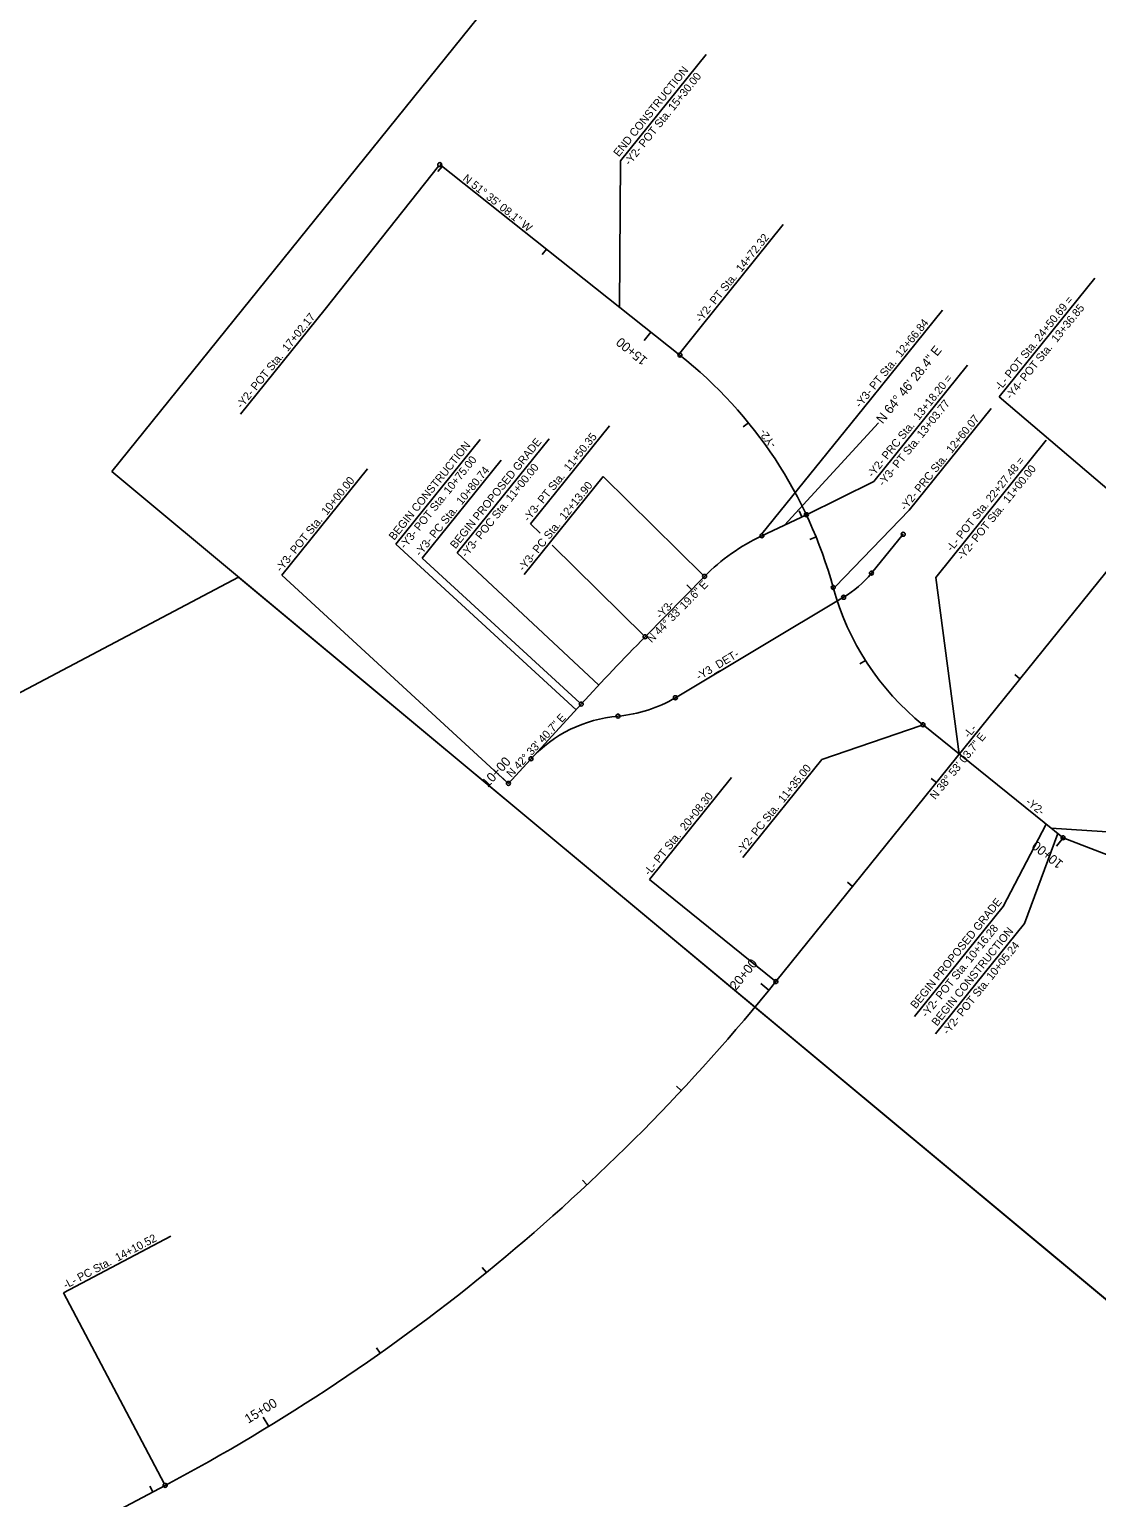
# Model space of a CAD drawing. Extents: x 1487008 to 1489561, y 497293 to 500195.
# Drawn here: x 1488013 to 1488814, y 498527 to 499628 of the extents above; entities that cross this region are included whole.
import ezdxf

# ---------------------------------------------------------------- set-up
doc = ezdxf.new("R2010")
doc.units = 0
for name, color, linetype in [('Prop Horizontal Alignment', 7, 'Continuous'), ('Prop Horizontal Alignment Direction Label', 7, 'Continuous'), ('Prop Horizontal Alignment Station Label', 7, 'Continuous'), ('Prop Horizontal Alignment Tick Label', 7, 'Continuous'), ('Prop Horizontal Alignment Tick Large', 7, 'Continuous'), ('Prop Horizontal Alignment Tick Small', 7, 'Continuous'), ('Scratch_Level_5', 7, 'Continuous')]:
    doc.layers.add(name, color=color, linetype=linetype)

msp = doc.modelspace()

# ---------------------------------------------------------------- linework, layer by layer
at = {"layer": 'Prop Horizontal Alignment'}
for p, q in [((1488501.1, 499383.6), (1488321, 499526.4)), ((1488573.1, 498913.9), (1489007.3, 499452.3)), ((1488562.6, 499248.1), (1488596, 499263.9)), ((1488644.8, 499220.1), (1488668.6, 499249.2)), ((1488475, 499172.4), (1488519.6, 499217.7)), ((1488497.7, 499126.7), (1488623.9, 499202)), ((1488372.5, 499062.5), (1488427.1, 499121.9)), ((1488788.6, 499021.7), (1488683.5, 499106.4)), ((1487752.2, 498344.1), (1488115, 498536.2))]:
    msp.add_line(p, q, dxfattribs=at)
for centre, radius, start, end in [((1488292.9, 499121.1), 335, 15.2846, 51.5856), ((1488626.5, 499112.4), 150, 115.2255, 135.4445), ((1488582.8, 499270.7), 80, 300.8418, 320.7375), ((1488809, 499262.1), 200, 195.2846, 231.1156), ((1489900.2, 497769.2), 2000, 135.4445, 137.4387), ((1488446.5, 499212.6), 100, 274.7509, 300.8418), ((1488463, 499013.2), 100, 94.7509, 137.4387), ((1487425, 499839.8), 1475, 297.895, 321.1156)]:
    msp.add_arc(centre, radius, start, end, dxfattribs=at)
at = {"layer": 'Prop Horizontal Alignment Direction Label'}
msp.add_line((1488779.7, 499028.8), (1488833.2, 499025.4), dxfattribs=at)
at = {"layer": 'Prop Horizontal Alignment Station Label'}
for p, q in [((1488456.6, 499529.3), (1488520.8, 499609)), ((1488320.1, 499525.2), (1488235.1, 499418.1)), ((1488455.9, 499419.4), (1488456.6, 499529.3)), ((1488517, 499405.1), (1488578.6, 499481.5)), ((1488740.7, 499352.4), (1488812.3, 499441.2)), ((1488171.6, 499339.3), (1488235.1, 499418.1)), ((1488638.8, 499343.8), (1488698, 499417.2)), ((1488501.1, 499385.1), (1488517, 499405.1)), ((1488646.7, 499288.9), (1488716.9, 499376)), ((1488740.7, 499352.4), (1488849.7, 499259.2)), ((1488562.6, 499249.6), (1488638.8, 499343.8)), ((1488673.1, 499267.3), (1488734.7, 499343.6)), ((1488389, 499257.1), (1488448.2, 499330.5)), ((1488650, 499332.7), (1488579.5, 499256.1)), ((1488288, 499241.8), (1488351.3, 499320.3)), ((1488334, 499235.4), (1488403, 499320.9)), ((1488693, 499216.9), (1488775.9, 499319.7)), ((1488307.9, 499231.4), (1488367.1, 499304.8)), ((1488202.5, 499218.5), (1488266.8, 499298.2)), ((1488384.4, 499219.1), (1488443.6, 499292.5)), ((1488443.6, 499292.5), (1488518.6, 499218.7)), ((1488596, 499263.9), (1488646.7, 499288.9)), ((1488617.5, 499209.8), (1488673.1, 499267.3)), ((1488396.2, 499250), (1488389, 499257.1)), ((1488423.2, 499117.7), (1488288, 499241.8)), ((1488474, 499173.4), (1488405.3, 499241)), ((1488426, 499122.9), (1488307.9, 499231.4)), ((1488440.2, 499136.1), (1488334, 499235.4)), ((1488371.4, 499063.5), (1488202.5, 499218.5)), ((1488693, 499216.9), (1488710.7, 499084.5)), ((1488682, 499105.9), (1488607.6, 499080.4)), ((1488548.4, 499007), (1488607.6, 499080.4)), ((1488478.3, 498990.4), (1488539.9, 499066.8)), ((1488775.9, 499031.9), (1488743.6, 498970.2)), ((1488759.5, 498957.4), (1488784.5, 499025)), ((1488788.6, 499021.7), (1488836.7, 499003.1)), ((1488572, 498914.8), (1488478.3, 498990.4)), ((1488677, 498887.7), (1488743.6, 498970.2)), ((1488692.9, 498874.8), (1488759.5, 498957.4)), ((1488038.7, 498680.5), (1488119.2, 498723)), ((1488114.3, 498537.5), (1488038.7, 498680.5))]:
    msp.add_line(p, q, dxfattribs=at)
for centre in [(1488321, 499526.4), (1488321, 499526.4), (1488501.1, 499383.6), (1488596, 499263.9), (1488562.6, 499248.1), (1488668.6, 499249.2), (1488519.6, 499217.7), (1488519.6, 499217.7), (1488644.8, 499220.1), (1488616.1, 499209.4), (1488623.9, 499202), (1488475, 499172.4), (1488475, 499172.4), (1488497.7, 499126.7), (1488427.1, 499121.9), (1488427.1, 499121.9), (1488454.7, 499112.9), (1488683.5, 499106.4), (1488683.5, 499106.4), (1488389.4, 499080.9), (1488372.5, 499062.5), (1488372.5, 499062.5), (1488788.6, 499021.7), (1488573.1, 498913.9), (1488115, 498536.2)]:
    msp.add_circle(centre, 1.5, dxfattribs=at)
at = {"layer": 'Prop Horizontal Alignment Tick Large'}
for p, q in [((1488479.4, 499400.8), (1488474.4, 499394.5)), ((1488372.5, 499062.5), (1488366.6, 499067.9)), ((1488372.5, 499062.5), (1488366.6, 499067.9)), ((1488788.6, 499021.7), (1488783.5, 499015.5)), ((1488567.9, 498907.4), (1488561.7, 498912.5)), ((1488192.8, 498580.4), (1488188.6, 498587.2))]:
    msp.add_line(p, q, dxfattribs=at)
at = {"layer": 'Prop Horizontal Alignment Tick Small'}
for p, q in [((1488322.7, 499525), (1488319.6, 499521.1)), ((1488401.1, 499462.9), (1488397.9, 499459)), ((1488552.5, 499332.9), (1488548.6, 499329.7)), ((1488592.6, 499262.2), (1488590.5, 499266.8)), ((1488603.3, 499247.2), (1488598.7, 499245.3)), ((1488509.9, 499207.8), (1488506.3, 499211.3)), ((1488509.9, 499207.8), (1488506.3, 499211.3)), ((1488640.3, 499154.7), (1488636.1, 499152)), ((1488440.2, 499136.1), (1488436.5, 499139.5)), ((1488440.2, 499136.1), (1488436.5, 499139.5)), ((1488756.2, 499140.9), (1488752.3, 499144.1)), ((1488710.7, 499084.5), (1488707.6, 499080.6)), ((1488710.7, 499084.5), (1488707.6, 499080.6)), ((1488693.5, 499063.1), (1488689.6, 499066.2)), ((1488630.7, 498985.2), (1488626.8, 498988.4)), ((1488502.1, 498832.1), (1488498.5, 498835.5)), ((1488431.4, 498761.5), (1488428, 498765.1)), ((1488356, 498695.8), (1488352.9, 498699.6)), ((1488276.4, 498635.3), (1488273.5, 498639.4)), ((1488105.8, 498531.3), (1488103.4, 498535.7))]:
    msp.add_line(p, q, dxfattribs=at)
at = {"layer": 'Scratch_Level_5'}
for p, q in [((1488882.1, 498624.3), (1488075.1, 499296.3)), ((1488907.6, 498603.2), (1488170.1, 499217.2))]:
    msp.add_line(p, q, dxfattribs=at)
for points in [[(1488075.1, 499296.3), (1488618.3, 499969.9), (1488753.4, 499860.9), (1488879, 500016.6), (1489561.3, 499466.4), (1488882.1, 498624.3), (1488882.1, 498624.3)], [(1488170.1, 499217.2), (1487167.7, 498687.9), (1487657.1, 497758.9), (1488983.5, 498459.3), (1488907.6, 498603.2)]]:
    msp.add_lwpolyline(points, dxfattribs=at)

# ---------------------------------------------------------------- texts
at = {"layer": 'Prop Horizontal Alignment Direction Label'}
for s, height, rotation, p in [('N 51%%d 35\' 08.1" W', 6, 321.5856, (1488337.7, 499515)), ('N 64%%d 46\' 28.4" E', 7, 51.1156, (1488653.2, 499331.6)), ('-Y2-', 6, 126.5382, (1488573.7, 499316.6)), ('N 44%%d 33\' 19.6" E', 6, 45.4445, (1488479.9, 499167.5)), ('-Y3-', 6, 45.4445, (1488486.6, 499185.4)), ('-Y3_DET-', 6, 30.8418, (1488515.5, 499139.6)), ('N 42%%d 33\' 40.7" E', 6, 47.4387, (1488374.8, 499066.5)), ('-L-', 6, 51.1156, (1488717.9, 499096)), ('N 38%%d 53\' 03.7" E', 6, 51.1156, (1488692.7, 499049.9)), ('-Y2-', 6, 321.1156, (1488760, 499047.6))]:
    msp.add_text(s, height=height, rotation=rotation, dxfattribs=at).set_placement(p)
at = {"layer": 'Prop Horizontal Alignment Station Label'}
for s, rotation, p in [('END CONSTRUCTION', 51.1156, (1488455.3, 499531.8)), ('-Y2- POT Sta. 15+30.00', 51.1156, (1488463.4, 499525.3)), ('-Y2- PT Sta.  14+72.32', 51.1156, (1488516.7, 499407.5)), ('-L- POT Sta. 24+50.69 =', 51.1156, (1488741.4, 499356.4)), ('-Y2- POT Sta.  17+02.17', 51.1156, (1488172.4, 499343.1)), ('-Y4- POT Sta.  13+36.85', 51.1156, (1488749.4, 499349.9)), ('-Y3- PT Sta.  12+66.84', 51.1156, (1488636.4, 499343.6)), ('-Y2- PRC Sta.  13+18.20 =', 51.1156, (1488645.7, 499291.3)), ('-Y3- PT Sta. 13+03.77', 51.1156, (1488653.8, 499284.8)), ('-Y2- PRC Sta.  12+60.07', 51.1156, (1488670.3, 499266.5)), ('-Y3- PT Sta.  11+50.35', 51.1156, (1488387.6, 499258.2)), ('BEGIN CONSTRUCTION', 51.1156, (1488286.8, 499244.3)), ('BEGIN PROPOSED GRADE', 51.1156, (1488332.8, 499237.9)), ('-Y3- POT Sta. 10+75.00', 51.1156, (1488294.9, 499237.8)), ('-L- POT Sta. 22+27.48 =', 51.1156, (1488705, 499235.9)), ('-Y3- POT Sta.  10+00.00', 51.1156, (1488201.9, 499220.5)), ('-Y3- PC Sta.  10+80.74', 51.1156, (1488306.4, 499232.3)), ('-Y3- POC Sta. 11+00.00', 51.1156, (1488340.9, 499231.4)), ('-Y2- POT Sta.  11+00.00', 51.1156, (1488713.1, 499229.3)), ('-Y3- PC Sta.  12+13.90', 51.1156, (1488383.8, 499221)), ('-Y2- PC Sta.  11+35.00', 51.1156, (1488547.8, 499009)), ('-L- PT Sta.  20+08.30', 51.1156, (1488478.1, 498992.9)), ('BEGIN PROPOSED GRADE', 51.1156, (1488678.1, 498893)), ('-Y2- POT Sta. 10+16.28', 51.1156, (1488686.2, 498886.5)), ('BEGIN CONSTRUCTION', 51.1156, (1488694, 498880.1)), ('-Y2- POT Sta. 10+05.24', 51.1156, (1488702.1, 498873.6)), ('-L- PC Sta.  14+10.52', 27.8351, (1488040.4, 498683.3))]:
    msp.add_text(s, height=6, rotation=rotation, dxfattribs=at).set_placement(p)
at = {"layer": 'Prop Horizontal Alignment Tick Label'}
for s, rotation, p in [('15+00', 140.736, (1488477.3, 499380.7)), ('10+00', 47.4387, (1488357, 499059)), ('10+00', 141.1156, (1488789.2, 499003.3)), ('20+00', 50.7932, (1488543.2, 498906.9)), ('15+00', 31.3709, (1488177.3, 498582.3))]:
    msp.add_text(s, height=7, rotation=rotation, dxfattribs=at).set_placement(p)

doc.saveas('drawing.dxf')
